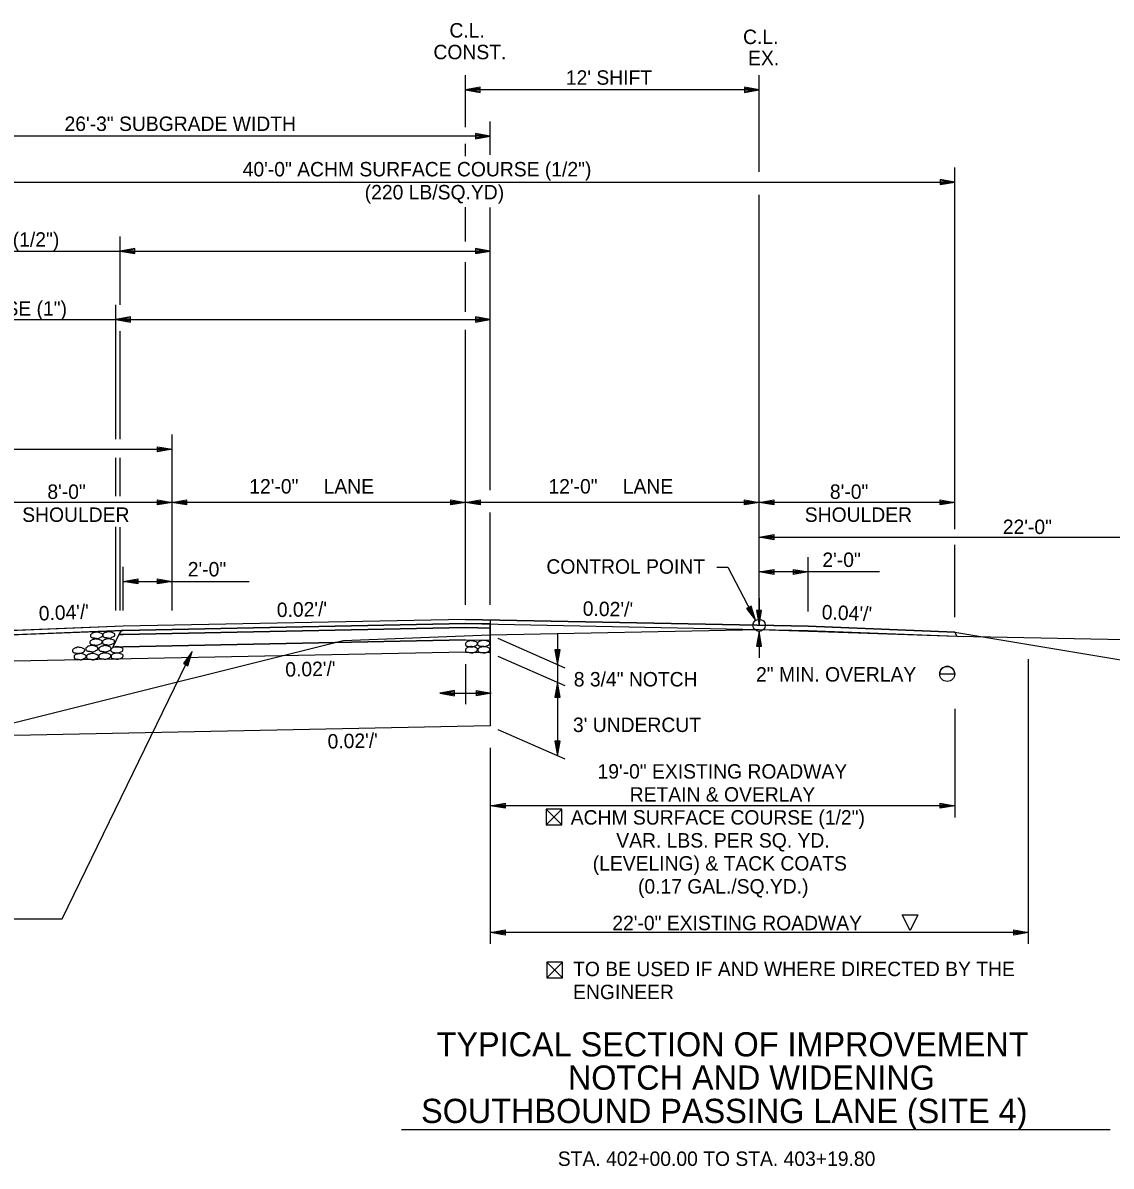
# Model space of a CAD drawing. Extents: x 1398565 to 1398920, y 1968324 to 1968581.
# Drawn here: x 1398824.08 to 1398868.57, y 1968379.98 to 1968426.72 of the extents above; entities that cross this region are included whole.
import ezdxf

# ---------------------------------------------------------------- set-up
doc = ezdxf.new("R2010")
doc.units = 0
for name, color, linetype in [('1', 7, 'Continuous'), ('10', 7, 'Continuous'), ('19', 7, 'Continuous'), ('42', 7, 'Continuous'), ('7', 7, 'Continuous'), ('Level 1', 7, 'Continuous'), ('Level 9', 7, 'Continuous')]:
    doc.layers.add(name, color=color, linetype=linetype)

# ---------------------------------------------------------------- blocks, each defined once
blk = doc.blocks.new('ROCKS')
at = {"layer": '1'}
blk.add_spline([(0.013, 0.06), (0.053, 0.053), (0.107, 0.033), (0.133, 0.013), (0.133, -0.007), (0.12, -0.033), (0.107, -0.04), (0.073, -0.053), (0.033, -0.067), (0.013, -0.067), (-0.02, -0.06), (-0.06, -0.053), (-0.087, -0.047), (-0.113, -0.02), (-0.113, -0.007), (-0.107, 0.02), (-0.087, 0.033), (-0.067, 0.047), (-0.033, 0.053), (-0.02, 0.06), (0.013, 0.06)], degree=3, dxfattribs=at)

msp = doc.modelspace()

# ---------------------------------------------------------------- linework, layer by layer
at = {"layer": '10'}
for p, q in [((1398861.56, 1968400.102), (1398862.171, 1968400.102)), ((1398845.474, 1968394.569), (1398846.115, 1968393.928)), ((1398846.115, 1968394.569), (1398845.474, 1968393.928)), ((1398845.855, 1968393.928), (1398845.866, 1968393.928)), ((1398845.499, 1968388.323), (1398846.141, 1968387.681)), ((1398846.141, 1968388.323), (1398845.499, 1968387.681)), ((1398845.881, 1968387.681), (1398845.892, 1968387.681))]:
    msp.add_line(p, q, dxfattribs=at)
for points in [[(1398845.866, 1968393.928), (1398846.115, 1968393.928), (1398846.115, 1968394.569), (1398845.474, 1968394.569), (1398845.474, 1968393.928), (1398845.855, 1968393.928)], [(1398845.892, 1968387.681), (1398846.141, 1968387.681), (1398846.141, 1968388.323), (1398845.499, 1968388.323), (1398845.499, 1968387.681), (1398845.881, 1968387.681)]]:
    msp.add_lwpolyline(points, dxfattribs=at)
msp.add_lwpolyline([(1398860.027, 1968390.262), (1398860.668, 1968390.262), (1398860.348, 1968389.62)], close=True, dxfattribs=at)
msp.add_circle((1398861.866, 1968400.102), 0.306, dxfattribs=at)
msp.add_arc((1398861.866, 1968400.102), 0.306, 0, 180, dxfattribs=at)
at = {"layer": '19'}
for p, q in [((1398842.776, 1968424.084), (1398842.176, 1968423.979)), ((1398842.776, 1968423.874), (1398842.776, 1968424.084)), ((1398853.576, 1968424.084), (1398853.576, 1968423.874)), ((1398854.176, 1968423.979), (1398853.576, 1968424.084)), ((1398854.176, 1968423.979), (1398842.176, 1968423.979)), ((1398842.176, 1968423.979), (1398842.776, 1968423.874)), ((1398842.776, 1968424.029), (1398842.336, 1968423.994)), ((1398842.336, 1968423.964), (1398842.776, 1968423.924)), ((1398854.016, 1968423.994), (1398853.576, 1968424.029)), ((1398853.576, 1968423.874), (1398854.176, 1968423.979)), ((1398853.576, 1968423.924), (1398854.016, 1968423.964)), ((1398843.176, 1968421.324), (1398843.176, 1968422.684)), ((1398843.176, 1968422.084), (1398816.893, 1968422.084)), ((1398842.576, 1968422.19), (1398842.576, 1968421.98)), ((1398843.176, 1968422.084), (1398842.576, 1968422.19)), ((1398843.016, 1968422.099), (1398842.576, 1968422.135)), ((1398842.576, 1968421.98), (1398843.176, 1968422.084)), ((1398842.576, 1968422.03), (1398843.016, 1968422.069)), ((1398862.176, 1968406.025), (1398862.176, 1968420.809)), ((1398822.176, 1968420.209), (1398862.176, 1968420.209)), ((1398861.576, 1968420.315), (1398861.576, 1968420.105)), ((1398862.176, 1968420.209), (1398861.576, 1968420.315)), ((1398862.016, 1968420.224), (1398861.576, 1968420.26)), ((1398861.576, 1968420.105), (1398862.176, 1968420.209)), ((1398861.576, 1968420.155), (1398862.016, 1968420.194)), ((1398843.176, 1968407.609), (1398843.176, 1968419.164)), ((1398828.049, 1968415.186), (1398828.049, 1968417.987)), ((1398809.771, 1968417.387), (1398843.176, 1968417.387)), ((1398828.649, 1968417.492), (1398828.049, 1968417.387)), ((1398828.049, 1968417.387), (1398828.649, 1968417.282)), ((1398828.649, 1968417.437), (1398828.209, 1968417.402)), ((1398828.209, 1968417.372), (1398828.649, 1968417.332)), ((1398828.649, 1968417.282), (1398828.649, 1968417.492)), ((1398842.576, 1968417.492), (1398842.576, 1968417.282)), ((1398843.176, 1968417.387), (1398842.576, 1968417.492)), ((1398843.016, 1968417.402), (1398842.576, 1968417.437)), ((1398842.576, 1968417.282), (1398843.176, 1968417.387)), ((1398842.576, 1968417.332), (1398843.016, 1968417.372)), ((1398827.879, 1968409.693), (1398827.879, 1968415.189)), ((1398810.671, 1968414.589), (1398843.176, 1968414.589)), ((1398828.479, 1968414.694), (1398827.879, 1968414.589)), ((1398827.879, 1968414.589), (1398828.479, 1968414.484)), ((1398828.479, 1968414.639), (1398828.039, 1968414.604)), ((1398828.039, 1968414.574), (1398828.479, 1968414.534)), ((1398828.479, 1968414.484), (1398828.479, 1968414.694)), ((1398842.576, 1968414.695), (1398842.576, 1968414.485)), ((1398843.176, 1968414.589), (1398842.576, 1968414.695)), ((1398843.016, 1968414.604), (1398842.576, 1968414.64)), ((1398842.576, 1968414.485), (1398843.176, 1968414.589)), ((1398842.576, 1968414.535), (1398843.016, 1968414.574)), ((1398828.049, 1968409.693), (1398828.049, 1968414.116)), ((1398830.176, 1968402.69), (1398830.176, 1968409.885)), ((1398806.176, 1968409.285), (1398830.176, 1968409.285)), ((1398829.576, 1968409.18), (1398829.576, 1968409.39)), ((1398829.576, 1968409.39), (1398830.176, 1968409.285)), ((1398829.576, 1968409.335), (1398830.016, 1968409.3)), ((1398830.176, 1968409.285), (1398829.576, 1968409.18)), ((1398830.016, 1968409.27), (1398829.576, 1968409.23)), ((1398827.879, 1968407.37), (1398827.879, 1968408.94)), ((1398828.049, 1968407.37), (1398828.049, 1968408.94)), ((1398830.181, 1968407.113), (1398816.893, 1968407.113)), ((1398829.576, 1968407.009), (1398829.576, 1968407.219)), ((1398829.576, 1968407.219), (1398830.176, 1968407.114)), ((1398829.576, 1968407.164), (1398830.016, 1968407.129)), ((1398830.176, 1968407.114), (1398829.576, 1968407.009)), ((1398830.016, 1968407.099), (1398829.576, 1968407.059)), ((1398830.17, 1968407.115), (1398830.77, 1968407.22)), ((1398830.77, 1968407.01), (1398830.17, 1968407.115)), ((1398842.176, 1968407.114), (1398830.176, 1968407.114)), ((1398830.33, 1968407.13), (1398830.77, 1968407.165)), ((1398830.77, 1968407.06), (1398830.33, 1968407.1)), ((1398830.77, 1968407.22), (1398830.77, 1968407.01)), ((1398841.576, 1968407.009), (1398841.576, 1968407.219)), ((1398841.576, 1968407.219), (1398842.176, 1968407.114)), ((1398841.576, 1968407.164), (1398842.016, 1968407.129)), ((1398842.176, 1968407.114), (1398841.576, 1968407.009)), ((1398842.016, 1968407.099), (1398841.576, 1968407.059)), ((1398842.176, 1968407.114), (1398842.776, 1968407.219)), ((1398842.776, 1968407.009), (1398842.176, 1968407.114)), ((1398854.176, 1968407.114), (1398842.176, 1968407.114)), ((1398842.336, 1968407.129), (1398842.776, 1968407.164)), ((1398842.776, 1968407.059), (1398842.336, 1968407.099)), ((1398842.776, 1968407.219), (1398842.776, 1968407.009)), ((1398853.576, 1968407.009), (1398853.576, 1968407.219)), ((1398853.576, 1968407.219), (1398854.176, 1968407.114)), ((1398853.576, 1968407.164), (1398854.016, 1968407.129)), ((1398854.176, 1968407.114), (1398853.576, 1968407.009)), ((1398854.016, 1968407.099), (1398853.576, 1968407.059)), ((1398854.176, 1968407.114), (1398854.776, 1968407.219)), ((1398862.176, 1968407.114), (1398854.176, 1968407.114)), ((1398854.776, 1968407.009), (1398854.176, 1968407.114)), ((1398854.336, 1968407.129), (1398854.776, 1968407.164)), ((1398854.776, 1968407.059), (1398854.336, 1968407.099)), ((1398854.776, 1968407.219), (1398854.776, 1968407.009)), ((1398861.576, 1968407.009), (1398861.576, 1968407.219)), ((1398861.576, 1968407.219), (1398862.176, 1968407.114)), ((1398861.576, 1968407.164), (1398862.016, 1968407.129)), ((1398862.176, 1968407.114), (1398861.576, 1968407.009)), ((1398862.016, 1968407.099), (1398861.576, 1968407.059)), ((1398843.176, 1968402.93), (1398843.176, 1968406.708)), ((1398827.879, 1968402.69), (1398827.879, 1968406.11)), ((1398828.049, 1968402.69), (1398828.049, 1968406.096)), ((1398854.176, 1968405.693), (1398854.776, 1968405.798)), ((1398854.176, 1968405.693), (1398876.176, 1968405.693)), ((1398854.776, 1968405.588), (1398854.176, 1968405.693)), ((1398854.336, 1968405.708), (1398854.776, 1968405.743)), ((1398854.776, 1968405.638), (1398854.336, 1968405.678)), ((1398854.776, 1968405.798), (1398854.776, 1968405.588)), ((1398862.176, 1968402.419), (1398862.176, 1968405.377)), ((1398828.176, 1968402.69), (1398828.176, 1968404.485)), ((1398856.176, 1968402.65), (1398856.176, 1968404.872)), ((1398828.176, 1968403.885), (1398828.776, 1968403.99)), ((1398828.776, 1968403.99), (1398828.776, 1968403.78)), ((1398829.576, 1968403.779), (1398829.576, 1968403.989)), ((1398829.576, 1968403.989), (1398830.176, 1968403.885)), ((1398854.176, 1968404.272), (1398854.776, 1968404.377)), ((1398859.101, 1968404.272), (1398854.176, 1968404.272)), ((1398854.776, 1968404.167), (1398854.176, 1968404.272)), ((1398854.336, 1968404.287), (1398854.776, 1968404.322)), ((1398854.776, 1968404.217), (1398854.336, 1968404.257)), ((1398854.776, 1968404.377), (1398854.776, 1968404.167)), ((1398855.576, 1968404.167), (1398855.576, 1968404.377)), ((1398855.576, 1968404.377), (1398856.176, 1968404.272)), ((1398855.576, 1968404.322), (1398856.016, 1968404.287)), ((1398856.176, 1968404.272), (1398855.576, 1968404.167)), ((1398856.016, 1968404.257), (1398855.576, 1968404.217)), ((1398828.176, 1968403.885), (1398833.323, 1968403.885)), ((1398828.776, 1968403.78), (1398828.176, 1968403.885)), ((1398828.336, 1968403.9), (1398828.776, 1968403.935)), ((1398828.776, 1968403.83), (1398828.336, 1968403.87)), ((1398829.576, 1968403.934), (1398830.016, 1968403.9)), ((1398830.176, 1968403.885), (1398829.576, 1968403.779)), ((1398830.016, 1968403.87), (1398829.576, 1968403.829)), ((1398854.176, 1968403.199), (1398854.176, 1968402.09)), ((1398853.852, 1968402.876), (1398853.667, 1968402.781)), ((1398853.667, 1968402.781), (1398854.03, 1968402.294)), ((1398853.709, 1968402.799), (1398853.944, 1968402.43)), ((1398853.968, 1968402.44), (1398853.807, 1968402.847)), ((1398854.03, 1968402.294), (1398853.852, 1968402.876)), ((1398854.281, 1968402.69), (1398854.071, 1968402.69)), ((1398854.071, 1968402.69), (1398854.176, 1968402.09)), ((1398854.126, 1968402.69), (1398854.161, 1968402.25)), ((1398854.176, 1968402.09), (1398854.281, 1968402.69)), ((1398854.191, 1968402.25), (1398854.231, 1968402.69)), ((1398842.176, 1968402.33), (1398828.176, 1968402.05)), ((1398842.176, 1968402.164), (1398828.176, 1968401.884)), ((1398842.176, 1968402.33), (1398856.176, 1968402.05)), ((1398842.176, 1968402.164), (1398856.176, 1968401.884)), ((1398843.176, 1968402.31), (1398843.176, 1968400.685)), ((1398828.176, 1968401.884), (1398822.091, 1968401.64)), ((1398828.176, 1968402.05), (1398822.176, 1968401.81)), ((1398828.006, 1968401.71), (1398827.751, 1968401.2)), ((1398828.006, 1968401.71), (1398827.751, 1968401.2)), ((1398828.091, 1968401.88), (1398828.006, 1968401.71)), ((1398828.176, 1968401.717), (1398828.006, 1968401.71)), ((1398842.176, 1968401.997), (1398828.176, 1968401.717)), ((1398842.176, 1968401.997), (1398843.176, 1968401.977)), ((1398843.176, 1968401.977), (1398842.176, 1968401.997)), ((1398843.176, 1968401.477), (1398843.176, 1968401.977)), ((1398845.932, 1968401.767), (1398845.932, 1968400.491)), ((1398854.176, 1968401.84), (1398854.071, 1968401.24)), ((1398854.161, 1968401.68), (1398854.126, 1968401.24)), ((1398854.281, 1968401.24), (1398854.176, 1968401.84)), ((1398854.176, 1968401.84), (1398854.176, 1968400.758)), ((1398854.231, 1968401.24), (1398854.191, 1968401.68)), ((1398856.176, 1968402.05), (1398862.176, 1968401.81)), ((1398856.176, 1968401.884), (1398862.261, 1968401.64)), ((1398862.176, 1968401.81), (1398876.176, 1968399.477)), ((1398862.176, 1968401.81), (1398862.261, 1968401.64)), ((1398828.176, 1968401.217), (1398827.751, 1968401.2)), ((1398842.176, 1968401.497), (1398828.176, 1968401.217)), ((1398842.176, 1968401.497), (1398843.176, 1968401.477)), ((1398842.176, 1968401.497), (1398843.176, 1968401.477)), ((1398843.492, 1968401.564), (1398846.234, 1968400.355)), ((1398854.071, 1968401.24), (1398854.281, 1968401.24)), ((1398842.176, 1968400.995), (1398816.893, 1968400.489)), ((1398825.682, 1968390.087), (1398831.002, 1968401.017)), ((1398831.002, 1968401.017), (1398830.638, 1968400.528)), ((1398830.92, 1968400.88), (1398830.687, 1968400.507)), ((1398830.781, 1968400.458), (1398830.945, 1968400.867)), ((1398830.825, 1968400.435), (1398831.002, 1968401.017)), ((1398842.176, 1968400.995), (1398843.176, 1968400.975)), ((1398843.492, 1968400.835), (1398846.234, 1968399.626)), ((1398846.037, 1968401.091), (1398845.827, 1968401.091)), ((1398845.827, 1968401.091), (1398845.932, 1968400.491)), ((1398845.882, 1968401.091), (1398845.917, 1968400.651)), ((1398845.932, 1968400.491), (1398846.037, 1968401.091)), ((1398845.947, 1968400.651), (1398845.987, 1968401.091)), ((1398830.638, 1968400.528), (1398830.825, 1968400.435)), ((1398843.176, 1968400.685), (1398843.176, 1968397.975)), ((1398845.932, 1968400.491), (1398845.932, 1968396.759)), ((1398865.19, 1968389.067), (1398865.19, 1968400.7)), ((1398845.932, 1968399.759), (1398845.827, 1968399.159)), ((1398845.917, 1968399.599), (1398845.882, 1968399.159)), ((1398846.037, 1968399.159), (1398845.932, 1968399.759)), ((1398845.987, 1968399.159), (1398845.947, 1968399.599)), ((1398845.827, 1968399.159), (1398846.037, 1968399.159)), ((1398862.176, 1968398.678), (1398862.176, 1968394.232)), ((1398843.176, 1968397.975), (1398804.345, 1968397.198)), ((1398843.492, 1968397.835), (1398846.234, 1968396.626)), ((1398843.19, 1968389.067), (1398843.19, 1968397.085)), ((1398846.037, 1968397.359), (1398845.827, 1968397.359)), ((1398845.827, 1968397.359), (1398845.932, 1968396.759)), ((1398845.882, 1968397.359), (1398845.917, 1968396.919)), ((1398845.932, 1968396.759), (1398846.037, 1968397.359)), ((1398845.947, 1968396.919), (1398845.987, 1968397.359)), ((1398843.19, 1968394.716), (1398843.79, 1968394.821)), ((1398843.79, 1968394.611), (1398843.19, 1968394.716)), ((1398862.176, 1968394.716), (1398843.19, 1968394.716)), ((1398843.35, 1968394.731), (1398843.79, 1968394.766)), ((1398843.79, 1968394.661), (1398843.35, 1968394.701)), ((1398843.79, 1968394.821), (1398843.79, 1968394.611)), ((1398861.576, 1968394.611), (1398861.576, 1968394.821)), ((1398861.576, 1968394.821), (1398862.176, 1968394.716)), ((1398861.576, 1968394.766), (1398862.016, 1968394.731)), ((1398862.176, 1968394.716), (1398861.576, 1968394.611)), ((1398862.016, 1968394.701), (1398861.576, 1968394.661)), ((1398822.153, 1968390.087), (1398825.682, 1968390.087)), ((1398843.19, 1968389.536), (1398843.79, 1968389.641)), ((1398865.19, 1968389.536), (1398843.19, 1968389.536)), ((1398843.79, 1968389.431), (1398843.19, 1968389.536)), ((1398843.35, 1968389.551), (1398843.79, 1968389.586)), ((1398843.79, 1968389.481), (1398843.35, 1968389.521)), ((1398843.79, 1968389.641), (1398843.79, 1968389.431)), ((1398864.59, 1968389.431), (1398864.59, 1968389.641)), ((1398864.59, 1968389.641), (1398865.19, 1968389.536)), ((1398864.59, 1968389.586), (1398865.03, 1968389.551)), ((1398865.19, 1968389.536), (1398864.59, 1968389.431)), ((1398865.03, 1968389.521), (1398864.59, 1968389.481)), ((1398839.557, 1968381.476), (1398868.536, 1968381.476))]:
    msp.add_line(p, q, dxfattribs=at)
for points in [[(1398852.451, 1968404.471), (1398852.897, 1968404.471), (1398854.03, 1968402.294)], [(1398842.176, 1968401.997), (1398828.176, 1968401.717), (1398828.006, 1968401.71)], [(1398827.751, 1968401.2), (1398828.176, 1968401.217), (1398842.176, 1968401.497)]]:
    msp.add_lwpolyline(points, dxfattribs=at)
for points in [[(1398822.093, 1968401.645), (1398828.176, 1968401.884), (1398842.176, 1968402.164), (1398856.176, 1968401.884), (1398862.261, 1968401.64), (1398862.176, 1968401.81), (1398856.176, 1968402.05), (1398842.176, 1968402.33), (1398828.176, 1968402.05), (1398822.176, 1968401.81)], [(1398828.091, 1968401.88), (1398828.006, 1968401.71), (1398828.176, 1968401.717), (1398842.176, 1968401.997), (1398843.176, 1968401.977), (1398843.176, 1968402.144), (1398842.176, 1968402.164), (1398828.175, 1968401.884)]]:
    msp.add_lwpolyline(points, close=True, dxfattribs=at)
at = {"layer": '42'}
for p, q in [((1398842.176, 1968400.497), (1398842.176, 1968398.865)), ((1398841.728, 1968399.421), (1398841.128, 1968399.316)), ((1398841.128, 1968399.316), (1398841.728, 1968399.211)), ((1398841.128, 1968399.316), (1398843.223, 1968399.316)), ((1398841.728, 1968399.366), (1398841.288, 1968399.331)), ((1398841.728, 1968399.211), (1398841.728, 1968399.421)), ((1398842.623, 1968399.211), (1398842.623, 1968399.421)), ((1398842.623, 1968399.421), (1398843.223, 1968399.316)), ((1398842.623, 1968399.366), (1398843.063, 1968399.331)), ((1398843.223, 1968399.316), (1398842.623, 1968399.211)), ((1398841.288, 1968399.301), (1398841.728, 1968399.261)), ((1398843.063, 1968399.301), (1398842.623, 1968399.261))]:
    msp.add_line(p, q, dxfattribs=at)
for points in [[(1398766.153, 1968395.354), (1398812.649, 1968395.354), (1398837.176, 1968401.464), (1398843.176, 1968401.704)], [(1398843.176, 1968401.704), (1398854.176, 1968401.924)], [(1398854.176, 1968401.924), (1398862.261, 1968401.64), (1398871.176, 1968401.464), (1398880.031, 1968399.003), (1398885.112, 1968399.545), (1398901.928, 1968399.456)]]:
    msp.add_lwpolyline(points, dxfattribs=at)
at = {"layer": '7'}
for p, q in [((1398842.176, 1968422.452), (1398842.176, 1968424.579)), ((1398854.176, 1968420.622), (1398854.176, 1968424.579)), ((1398842.176, 1968421.269), (1398842.176, 1968421.776)), ((1398854.176, 1968402.33), (1398854.176, 1968419.692)), ((1398842.176, 1968417.777), (1398842.176, 1968419.185)), ((1398842.176, 1968414.904), (1398842.176, 1968416.932)), ((1398842.176, 1968402.93), (1398842.176, 1968414.172))]:
    msp.add_line(p, q, dxfattribs=at)
at = {"layer": 'Level 9'}
msp.add_circle((1398854.176, 1968402.09), 0.25, dxfattribs=at)

# ---------------------------------------------------------------- block references
at = {"layer": 'Level 1', "xscale": 2.011654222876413, "yscale": 2.011654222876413, "rotation": 1.8263814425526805}
for p in [(1398827.072, 1968401.687), (1398827.57, 1968401.702), (1398826.334, 1968401.072), (1398826.877, 1968401.142), (1398827.045, 1968401.408), (1398827.411, 1968401.138), (1398827.557, 1968401.419), (1398827.901, 1968401.094), (1398842.396, 1968401.339), (1398842.396, 1968401.097), (1398842.895, 1968401.354), (1398842.9, 1968401.096), (1398826.394, 1968400.817), (1398826.898, 1968400.816), (1398827.403, 1968400.837), (1398827.907, 1968400.836)]:
    msp.add_blockref('ROCKS', p, dxfattribs=at)

# ---------------------------------------------------------------- texts
at = {"layer": '10'}
for s, height, p in [('8\'-0" ', 0.59, (1398825.077, 1968407.258)), ('12\'-0" ', 0.59, (1398833.333, 1968407.477)), ('LANE', 0.59, (1398836.372, 1968407.477)), ('12\'-0" ', 0.59, (1398845.564, 1968407.477)), ('LANE', 0.59, (1398848.602, 1968407.477)), ('8\'-0" ', 0.59, (1398857.071, 1968407.259)), ('SHOULDER', 0.59, (1398824.05, 1968406.318)), ('SHOULDER', 0.59, (1398856.045, 1968406.319)), ('22\'-0"', 0.59, (1398864.14, 1968405.821)), ('2\'-0"', 0.59, (1398856.764, 1968404.475)), ('2\'-0"', 0.59, (1398830.818, 1968404.088)), ('CONTROL POINT', 0.59001, (1398845.48, 1968404.199)), ('2" MIN. OVERLAY', 0.59001, (1398854.052, 1968399.79)), ('8 3/4" NOTCH', 0.59001, (1398846.6, 1968399.591)), ("3' UNDERCUT", 0.59001, (1398846.567, 1968397.728)), ('19\'-0" EXISTING ROADWAY', 0.59001, (1398847.57, 1968395.824)), ('RETAIN & OVERLAY', 0.59001, (1398848.885, 1968394.884)), ('ACHM SURFACE COURSE (1/2")', 0.59001, (1398846.474, 1968393.944)), ('VAR. LBS. PER SQ. YD.', 0.59001, (1398848.337, 1968393.004)), ('(LEVELING) & TACK COATS', 0.59001, (1398847.375, 1968392.064)), ('(0.17 GAL./SQ.YD.)', 0.59001, (1398849.224, 1968391.124)), ('22\'-0" EXISTING ROADWAY', 0.59001, (1398848.175, 1968389.628)), ('TO BE USED IF AND WHERE DIRECTED BY THE ', 0.59001, (1398846.572, 1968387.749)), ('ENGINEER', 0.59, (1398846.572, 1968386.809)), ('STA. 402+00.00 TO STA. 403+19.80', 0.59001, (1398845.947, 1968379.992))]:
    msp.add_text(s, height=height, rotation=360, dxfattribs=at).set_placement(p)
at = {"layer": '19'}
for p in [(1398841.516, 1968426.117), (1398853.521, 1968425.85)]:
    msp.add_text('C.L.', height=0.59, dxfattribs=at).set_placement(p)
for s, height, rotation, p in [('CONST.', 0.59, 360, (1398840.862, 1968425.229)), ('EX.', 0.59, 360, (1398853.726, 1968424.983)), ("12' SHIFT", 0.59, 360, (1398846.276, 1968424.186)), ("0.02'/'", 0.59, 1.1458, (1398834.464, 1968402.425)), ("0.02'/'", 0.59, 358.8542, (1398846.962, 1968402.484)), ("0.04'/'", 0.59, 2.2906, (1398824.737, 1968402.282)), ("0.04'/'", 0.59, 357.7094, (1398856.728, 1968402.34)), ("0.02'/'", 0.59, 1.1458, (1398834.81, 1968399.988)), ("0.02'/'", 0.59, 1.1458, (1398836.54, 1968397.051)), ('TYPICAL SECTION OF IMPROVEMENT', 0.98999, 360, (1398840.994, 1968384.468)), ('NOTCH AND WIDENING', 0.98999, 360, (1398846.357, 1968383.107)), ('SOUTHBOUND PASSING LANE (SITE 4)', 0.98999, 360, (1398840.358, 1968381.746))]:
    msp.add_text(s, height=height, rotation=rotation, dxfattribs=at).set_placement(p)
at = {"layer": '42'}
for s, p in [('26\'-3" SUBGRADE WIDTH', (1398825.779, 1968422.297)), ('40\'-0" ACHM SURFACE COURSE (1/2")', (1398833.063, 1968420.44)), ('(220 LB/SQ.YD)', (1398838.052, 1968419.5)), ('15\'-1 1/2" ACHM SURFACE COURSE (1/2")', (1398809.992, 1968417.566)), ('15\'-3 1/2" ACHM BINDER COURSE (1")', (1398811.754, 1968414.747))]:
    msp.add_text(s, height=0.59001, rotation=360, dxfattribs=at).set_placement(p)

doc.saveas('drawing.dxf')
